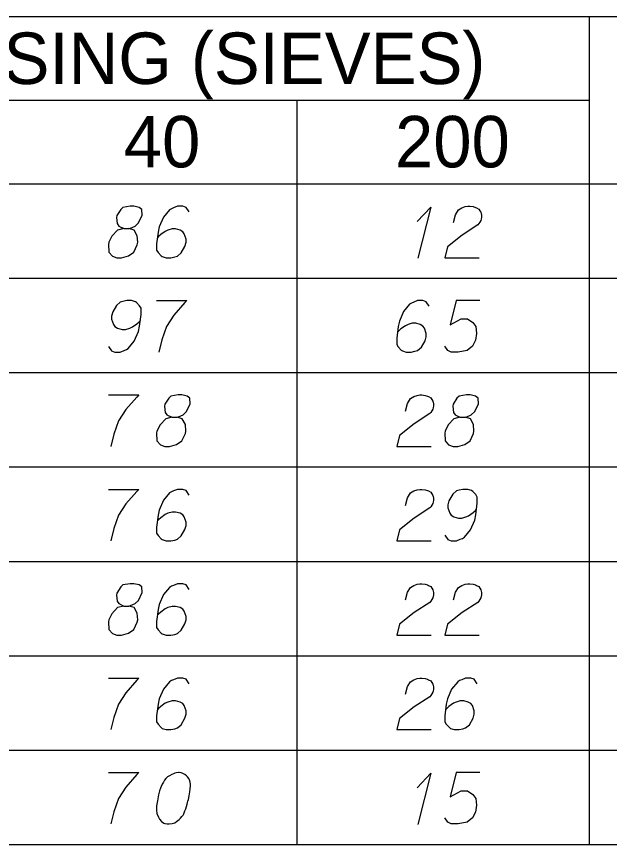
# Model space of a CAD drawing. Extents: x 2074207 to 2076812, y 516372 to 523312.
# Drawn here: x 2076678.5 to 2076733.8, y 517302 to 517379.2 of the extents above; entities that cross this region are included whole.
import ezdxf

# ---------------------------------------------------------------- set-up
doc = ezdxf.new("R2010")
doc.units = 0
for name, color, linetype in [('Prop DirtTable_ Soil Test Results - Outline (Major)', 7, 'Continuous'), ('Prop DirtTable_ Soil Test Results - Outline (Minor)', 7, 'Continuous'), ('Prop DirtTable_ Soil Test Results - Tx (Header - Small)', 7, 'Continuous'), ('Prop DirtTable_ Soil Test Results - Tx (Sample Data)', 7, 'Continuous')]:
    doc.layers.add(name, color=color, linetype=linetype)

msp = doc.modelspace()

# ---------------------------------------------------------------- linework, layer by layer
at = {"layer": 'Prop DirtTable_ Soil Test Results - Outline (Major)'}
for p, q in [((2076260.609, 517363.585), (2076811.903, 517363.585)), ((2076260.609, 517363.585), (2076811.903, 517363.585)), ((2076260.609, 517301.985), (2076811.903, 517301.985))]:
    msp.add_line(p, q, dxfattribs=at)
at = {"layer": 'Prop DirtTable_ Soil Test Results - Outline (Minor)'}
for p, q in [((2076260.609, 517379.185), (2076811.903, 517379.185)), ((2076731.93, 517379.185), (2076731.93, 517354.785)), ((2076526.074, 517371.385), (2076731.93, 517371.385)), ((2076704.671, 517371.385), (2076704.671, 517354.785)), ((2076260.609, 517354.785), (2076811.903, 517354.785)), ((2076260.609, 517354.785), (2076811.903, 517354.785)), ((2076704.671, 517354.785), (2076704.671, 517345.985)), ((2076731.93, 517354.785), (2076731.93, 517345.985)), ((2076260.609, 517345.985), (2076811.903, 517345.985)), ((2076260.609, 517345.985), (2076811.903, 517345.985)), ((2076704.671, 517345.985), (2076704.671, 517337.185)), ((2076731.93, 517345.985), (2076731.93, 517337.185)), ((2076260.609, 517337.185), (2076811.903, 517337.185)), ((2076260.609, 517337.185), (2076811.903, 517337.185)), ((2076704.671, 517337.185), (2076704.671, 517328.385)), ((2076731.93, 517337.185), (2076731.93, 517328.385)), ((2076260.609, 517328.385), (2076811.903, 517328.385)), ((2076260.609, 517328.385), (2076811.903, 517328.385)), ((2076704.671, 517328.385), (2076704.671, 517319.585)), ((2076731.93, 517328.385), (2076731.93, 517319.585)), ((2076260.609, 517319.585), (2076811.903, 517319.585)), ((2076260.609, 517319.585), (2076811.903, 517319.585)), ((2076704.671, 517319.585), (2076704.671, 517310.785)), ((2076731.93, 517319.585), (2076731.93, 517310.785)), ((2076260.609, 517310.785), (2076811.903, 517310.785)), ((2076260.609, 517310.785), (2076811.903, 517310.785)), ((2076704.671, 517310.785), (2076704.671, 517301.985)), ((2076731.93, 517310.785), (2076731.93, 517301.985)), ((2076260.609, 517301.985), (2076811.903, 517301.985))]:
    msp.add_line(p, q, dxfattribs=at)
at = {"layer": 'Prop DirtTable_ Soil Test Results - Tx (Sample Data)'}
for points in [[(2076688.527, 517359.419), (2076689.02, 517359.419), (2076689.162, 517359.457), (2076689.585, 517359.646), (2076689.902, 517359.948), (2076690.255, 517360.667), (2076690.22, 517361.196), (2076689.973, 517361.385), (2076689.479, 517361.498), (2076689.126, 517361.498), (2076688.456, 517361.385), (2076688.244, 517361.196), (2076687.892, 517360.629), (2076687.856, 517360.44), (2076687.927, 517359.873), (2076688.068, 517359.646), (2076688.527, 517359.419), (2076687.962, 517359.268), (2076687.433, 517358.701), (2076687.151, 517358.134), (2076687.116, 517357.945), (2076687.151, 517357.227), (2076687.468, 517356.849), (2076687.892, 517356.698), (2076688.315, 517356.698), (2076688.985, 517356.887), (2076689.479, 517357.227), (2076689.797, 517357.907), (2076689.832, 517358.134), (2076689.797, 517358.739), (2076689.514, 517359.268), (2076689.02, 517359.419)], [(2076694.629, 517360.969), (2076694.347, 517361.385), (2076694.03, 517361.498), (2076693.536, 517361.498), (2076693.183, 517361.347), (2076692.971, 517361.271), (2076692.795, 517361.158), (2076692.231, 517360.478), (2076691.843, 517359.57), (2076691.737, 517359.079), (2076691.596, 517357.983), (2076691.596, 517357.416), (2076691.737, 517357.189), (2076692.019, 517356.887), (2076692.125, 517356.811), (2076692.478, 517356.698), (2076692.936, 517356.698), (2076693.289, 517356.774), (2076693.536, 517356.849), (2076693.889, 517357.152), (2076694.241, 517357.756), (2076694.347, 517358.134), (2076694.347, 517358.437), (2076694.171, 517358.928), (2076694.03, 517359.117), (2076693.783, 517359.268), (2076693.359, 517359.381), (2076693.042, 517359.381), (2076692.654, 517359.268), (2076692.407, 517359.155), (2076691.984, 517358.852), (2076691.772, 517358.663), (2076691.666, 517358.55)], [(2076715.9, 517360.062), (2076717.17, 517361.422), (2076715.971, 517356.66)], [(2076719.287, 517359.986), (2076719.463, 517360.704), (2076719.746, 517361.158), (2076720.063, 517361.347), (2076720.38, 517361.46), (2076720.627, 517361.498), (2076720.804, 517361.498), (2076721.121, 517361.46), (2076721.333, 517361.385), (2076721.439, 517361.347), (2076721.65, 517361.233), (2076721.756, 517361.082), (2076721.827, 517360.931), (2076721.862, 517360.818), (2076721.897, 517360.667), (2076721.897, 517360.478), (2076721.862, 517360.289), (2076721.827, 517360.175), (2076721.756, 517360.024), (2076721.65, 517359.873), (2076721.545, 517359.759), (2076720.098, 517358.815), (2076718.723, 517357.718), (2076718.476, 517356.698), (2076721.686, 517356.698)], [(2076687.116, 517348.427), (2076687.398, 517348.011), (2076687.715, 517347.898), (2076688.209, 517347.898), (2076688.562, 517348.049), (2076688.774, 517348.125), (2076688.95, 517348.238), (2076689.514, 517348.918), (2076689.902, 517349.826), (2076690.008, 517350.317), (2076690.149, 517351.413), (2076690.149, 517351.98), (2076690.008, 517352.207), (2076689.726, 517352.509), (2076689.62, 517352.585), (2076689.267, 517352.698), (2076688.809, 517352.698), (2076688.456, 517352.622), (2076688.209, 517352.547), (2076687.856, 517352.244), (2076687.504, 517351.64), (2076687.398, 517351.262), (2076687.398, 517350.959), (2076687.574, 517350.468), (2076687.715, 517350.279), (2076687.962, 517350.128), (2076688.386, 517350.015), (2076688.703, 517350.015), (2076689.091, 517350.128), (2076689.338, 517350.241), (2076689.761, 517350.544), (2076689.973, 517350.733), (2076690.079, 517350.846)], [(2076691.596, 517352.698), (2076694.418, 517352.698), (2076694.241, 517352.509), (2076693.218, 517351.337), (2076692.513, 517350.279), (2076692.089, 517349.032), (2076691.807, 517347.898)], [(2076717.029, 517352.169), (2076716.747, 517352.585), (2076716.43, 517352.698), (2076715.936, 517352.698), (2076715.583, 517352.547), (2076715.371, 517352.471), (2076715.195, 517352.358), (2076714.631, 517351.678), (2076714.243, 517350.77), (2076714.137, 517350.279), (2076713.996, 517349.183), (2076713.996, 517348.616), (2076714.137, 517348.389), (2076714.419, 517348.087), (2076714.525, 517348.011), (2076714.878, 517347.898), (2076715.336, 517347.898), (2076715.689, 517347.974), (2076715.936, 517348.049), (2076716.289, 517348.352), (2076716.641, 517348.956), (2076716.747, 517349.334), (2076716.747, 517349.637), (2076716.571, 517350.128), (2076716.43, 517350.317), (2076716.183, 517350.468), (2076715.759, 517350.581), (2076715.442, 517350.581), (2076715.054, 517350.468), (2076714.807, 517350.355), (2076714.384, 517350.052), (2076714.172, 517349.863), (2076714.066, 517349.75)], [(2076721.756, 517352.698), (2076719.534, 517352.698), (2076718.969, 517350.43), (2076719.992, 517350.997), (2076720.592, 517350.997), (2076721.086, 517350.657), (2076721.368, 517350.279), (2076721.439, 517349.637), (2076721.333, 517348.994), (2076721.051, 517348.465), (2076720.557, 517348.049), (2076719.71, 517347.898), (2076719.075, 517347.898), (2076718.758, 517348.049), (2076718.476, 517348.465)], [(2076687.116, 517343.898), (2076689.938, 517343.898), (2076689.761, 517343.709), (2076688.738, 517342.537), (2076688.033, 517341.479), (2076687.609, 517340.232), (2076687.327, 517339.098)], [(2076693.007, 517341.819), (2076693.5, 517341.819), (2076693.642, 517341.857), (2076694.065, 517342.046), (2076694.382, 517342.348), (2076694.735, 517343.067), (2076694.7, 517343.596), (2076694.453, 517343.785), (2076693.959, 517343.898), (2076693.606, 517343.898), (2076692.936, 517343.785), (2076692.724, 517343.596), (2076692.372, 517343.029), (2076692.336, 517342.84), (2076692.407, 517342.273), (2076692.548, 517342.046), (2076693.007, 517341.819), (2076692.442, 517341.668), (2076691.913, 517341.101), (2076691.631, 517340.534), (2076691.596, 517340.345), (2076691.631, 517339.627), (2076691.948, 517339.249), (2076692.372, 517339.098), (2076692.795, 517339.098), (2076693.465, 517339.287), (2076693.959, 517339.627), (2076694.277, 517340.307), (2076694.312, 517340.534), (2076694.277, 517341.139), (2076693.994, 517341.668), (2076693.5, 517341.819)], [(2076714.807, 517342.386), (2076714.983, 517343.104), (2076715.266, 517343.558), (2076715.583, 517343.747), (2076715.9, 517343.86), (2076716.147, 517343.898), (2076716.324, 517343.898), (2076716.641, 517343.86), (2076716.853, 517343.785), (2076716.959, 517343.747), (2076717.17, 517343.633), (2076717.276, 517343.482), (2076717.347, 517343.331), (2076717.382, 517343.218), (2076717.417, 517343.067), (2076717.417, 517342.878), (2076717.382, 517342.689), (2076717.347, 517342.575), (2076717.276, 517342.424), (2076717.17, 517342.273), (2076717.065, 517342.159), (2076715.618, 517341.215), (2076714.243, 517340.118), (2076713.996, 517339.098), (2076717.206, 517339.098)], [(2076719.887, 517341.819), (2076720.38, 517341.819), (2076720.522, 517341.857), (2076720.945, 517342.046), (2076721.262, 517342.348), (2076721.615, 517343.067), (2076721.58, 517343.596), (2076721.333, 517343.785), (2076720.839, 517343.898), (2076720.486, 517343.898), (2076719.816, 517343.785), (2076719.604, 517343.596), (2076719.252, 517343.029), (2076719.216, 517342.84), (2076719.287, 517342.273), (2076719.428, 517342.046), (2076719.887, 517341.819), (2076719.322, 517341.668), (2076718.793, 517341.101), (2076718.511, 517340.534), (2076718.476, 517340.345), (2076718.511, 517339.627), (2076718.828, 517339.249), (2076719.252, 517339.098), (2076719.675, 517339.098), (2076720.345, 517339.287), (2076720.839, 517339.627), (2076721.157, 517340.307), (2076721.192, 517340.534), (2076721.157, 517341.139), (2076720.874, 517341.668), (2076720.38, 517341.819)], [(2076687.116, 517335.098), (2076689.938, 517335.098), (2076689.761, 517334.909), (2076688.738, 517333.737), (2076688.033, 517332.679), (2076687.609, 517331.432), (2076687.327, 517330.298)], [(2076694.629, 517334.569), (2076694.347, 517334.985), (2076694.03, 517335.098), (2076693.536, 517335.098), (2076693.183, 517334.947), (2076692.971, 517334.871), (2076692.795, 517334.758), (2076692.231, 517334.078), (2076691.843, 517333.17), (2076691.737, 517332.679), (2076691.596, 517331.583), (2076691.596, 517331.016), (2076691.737, 517330.789), (2076692.019, 517330.487), (2076692.125, 517330.411), (2076692.478, 517330.298), (2076692.936, 517330.298), (2076693.289, 517330.374), (2076693.536, 517330.449), (2076693.889, 517330.752), (2076694.241, 517331.356), (2076694.347, 517331.734), (2076694.347, 517332.037), (2076694.171, 517332.528), (2076694.03, 517332.717), (2076693.783, 517332.868), (2076693.359, 517332.981), (2076693.042, 517332.981), (2076692.654, 517332.868), (2076692.407, 517332.755), (2076691.984, 517332.452), (2076691.772, 517332.263), (2076691.666, 517332.15)], [(2076714.807, 517333.586), (2076714.983, 517334.304), (2076715.266, 517334.758), (2076715.583, 517334.947), (2076715.9, 517335.06), (2076716.147, 517335.098), (2076716.324, 517335.098), (2076716.641, 517335.06), (2076716.853, 517334.985), (2076716.959, 517334.947), (2076717.17, 517334.833), (2076717.276, 517334.682), (2076717.347, 517334.531), (2076717.382, 517334.418), (2076717.417, 517334.267), (2076717.417, 517334.078), (2076717.382, 517333.889), (2076717.347, 517333.775), (2076717.276, 517333.624), (2076717.17, 517333.473), (2076717.065, 517333.359), (2076715.618, 517332.415), (2076714.243, 517331.318), (2076713.996, 517330.298), (2076717.206, 517330.298)], [(2076718.476, 517330.827), (2076718.758, 517330.411), (2076719.075, 517330.298), (2076719.569, 517330.298), (2076719.922, 517330.449), (2076720.134, 517330.525), (2076720.31, 517330.638), (2076720.874, 517331.318), (2076721.262, 517332.226), (2076721.368, 517332.717), (2076721.509, 517333.813), (2076721.509, 517334.38), (2076721.368, 517334.607), (2076721.086, 517334.909), (2076720.98, 517334.985), (2076720.627, 517335.098), (2076720.169, 517335.098), (2076719.816, 517335.022), (2076719.569, 517334.947), (2076719.216, 517334.644), (2076718.864, 517334.04), (2076718.758, 517333.662), (2076718.758, 517333.359), (2076718.934, 517332.868), (2076719.075, 517332.679), (2076719.322, 517332.528), (2076719.746, 517332.415), (2076720.063, 517332.415), (2076720.451, 517332.528), (2076720.698, 517332.641), (2076721.121, 517332.944), (2076721.333, 517333.133), (2076721.439, 517333.246)], [(2076688.527, 517324.219), (2076689.02, 517324.219), (2076689.162, 517324.257), (2076689.585, 517324.446), (2076689.902, 517324.748), (2076690.255, 517325.467), (2076690.22, 517325.996), (2076689.973, 517326.185), (2076689.479, 517326.298), (2076689.126, 517326.298), (2076688.456, 517326.185), (2076688.244, 517325.996), (2076687.892, 517325.429), (2076687.856, 517325.24), (2076687.927, 517324.673), (2076688.068, 517324.446), (2076688.527, 517324.219), (2076687.962, 517324.068), (2076687.433, 517323.501), (2076687.151, 517322.934), (2076687.116, 517322.745), (2076687.151, 517322.027), (2076687.468, 517321.649), (2076687.892, 517321.498), (2076688.315, 517321.498), (2076688.985, 517321.687), (2076689.479, 517322.027), (2076689.797, 517322.707), (2076689.832, 517322.934), (2076689.797, 517323.539), (2076689.514, 517324.068), (2076689.02, 517324.219)], [(2076694.629, 517325.769), (2076694.347, 517326.185), (2076694.03, 517326.298), (2076693.536, 517326.298), (2076693.183, 517326.147), (2076692.971, 517326.071), (2076692.795, 517325.958), (2076692.231, 517325.278), (2076691.843, 517324.37), (2076691.737, 517323.879), (2076691.596, 517322.783), (2076691.596, 517322.216), (2076691.737, 517321.989), (2076692.019, 517321.687), (2076692.125, 517321.611), (2076692.478, 517321.498), (2076692.936, 517321.498), (2076693.289, 517321.574), (2076693.536, 517321.649), (2076693.889, 517321.952), (2076694.241, 517322.556), (2076694.347, 517322.934), (2076694.347, 517323.237), (2076694.171, 517323.728), (2076694.03, 517323.917), (2076693.783, 517324.068), (2076693.359, 517324.181), (2076693.042, 517324.181), (2076692.654, 517324.068), (2076692.407, 517323.955), (2076691.984, 517323.652), (2076691.772, 517323.463), (2076691.666, 517323.35)], [(2076714.807, 517324.786), (2076714.983, 517325.504), (2076715.266, 517325.958), (2076715.583, 517326.147), (2076715.9, 517326.26), (2076716.147, 517326.298), (2076716.324, 517326.298), (2076716.641, 517326.26), (2076716.853, 517326.185), (2076716.959, 517326.147), (2076717.17, 517326.033), (2076717.276, 517325.882), (2076717.347, 517325.731), (2076717.382, 517325.618), (2076717.417, 517325.467), (2076717.417, 517325.278), (2076717.382, 517325.089), (2076717.347, 517324.975), (2076717.276, 517324.824), (2076717.17, 517324.673), (2076717.065, 517324.559), (2076715.618, 517323.615), (2076714.243, 517322.518), (2076713.996, 517321.498), (2076717.206, 517321.498)], [(2076719.287, 517324.786), (2076719.463, 517325.504), (2076719.746, 517325.958), (2076720.063, 517326.147), (2076720.38, 517326.26), (2076720.627, 517326.298), (2076720.804, 517326.298), (2076721.121, 517326.26), (2076721.333, 517326.185), (2076721.439, 517326.147), (2076721.65, 517326.033), (2076721.756, 517325.882), (2076721.827, 517325.731), (2076721.862, 517325.618), (2076721.897, 517325.467), (2076721.897, 517325.278), (2076721.862, 517325.089), (2076721.827, 517324.975), (2076721.756, 517324.824), (2076721.65, 517324.673), (2076721.545, 517324.559), (2076720.098, 517323.615), (2076718.723, 517322.518), (2076718.476, 517321.498), (2076721.686, 517321.498)], [(2076687.116, 517317.498), (2076689.938, 517317.498), (2076689.761, 517317.309), (2076688.738, 517316.137), (2076688.033, 517315.079), (2076687.609, 517313.832), (2076687.327, 517312.698)], [(2076694.629, 517316.969), (2076694.347, 517317.385), (2076694.03, 517317.498), (2076693.536, 517317.498), (2076693.183, 517317.347), (2076692.971, 517317.271), (2076692.795, 517317.158), (2076692.231, 517316.478), (2076691.843, 517315.57), (2076691.737, 517315.079), (2076691.596, 517313.983), (2076691.596, 517313.416), (2076691.737, 517313.189), (2076692.019, 517312.887), (2076692.125, 517312.811), (2076692.478, 517312.698), (2076692.936, 517312.698), (2076693.289, 517312.774), (2076693.536, 517312.849), (2076693.889, 517313.152), (2076694.241, 517313.756), (2076694.347, 517314.134), (2076694.347, 517314.437), (2076694.171, 517314.928), (2076694.03, 517315.117), (2076693.783, 517315.268), (2076693.359, 517315.381), (2076693.042, 517315.381), (2076692.654, 517315.268), (2076692.407, 517315.155), (2076691.984, 517314.852), (2076691.772, 517314.663), (2076691.666, 517314.55)], [(2076714.807, 517315.986), (2076714.983, 517316.704), (2076715.266, 517317.158), (2076715.583, 517317.347), (2076715.9, 517317.46), (2076716.147, 517317.498), (2076716.324, 517317.498), (2076716.641, 517317.46), (2076716.853, 517317.385), (2076716.959, 517317.347), (2076717.17, 517317.233), (2076717.276, 517317.082), (2076717.347, 517316.931), (2076717.382, 517316.818), (2076717.417, 517316.667), (2076717.417, 517316.478), (2076717.382, 517316.289), (2076717.347, 517316.175), (2076717.276, 517316.024), (2076717.17, 517315.873), (2076717.065, 517315.759), (2076715.618, 517314.815), (2076714.243, 517313.718), (2076713.996, 517312.698), (2076717.206, 517312.698)], [(2076721.509, 517316.969), (2076721.227, 517317.385), (2076720.91, 517317.498), (2076720.416, 517317.498), (2076720.063, 517317.347), (2076719.851, 517317.271), (2076719.675, 517317.158), (2076719.111, 517316.478), (2076718.723, 517315.57), (2076718.617, 517315.079), (2076718.476, 517313.983), (2076718.476, 517313.416), (2076718.617, 517313.189), (2076718.899, 517312.887), (2076719.005, 517312.811), (2076719.358, 517312.698), (2076719.816, 517312.698), (2076720.169, 517312.774), (2076720.416, 517312.849), (2076720.769, 517313.152), (2076721.121, 517313.756), (2076721.227, 517314.134), (2076721.227, 517314.437), (2076721.051, 517314.928), (2076720.91, 517315.117), (2076720.663, 517315.268), (2076720.239, 517315.381), (2076719.922, 517315.381), (2076719.534, 517315.268), (2076719.287, 517315.155), (2076718.864, 517314.852), (2076718.652, 517314.663), (2076718.546, 517314.55)], [(2076687.116, 517308.698), (2076689.938, 517308.698), (2076689.761, 517308.509), (2076688.738, 517307.337), (2076688.033, 517306.279), (2076687.609, 517305.032), (2076687.327, 517303.898)], [(2076693.712, 517308.698), (2076693.642, 517308.698), (2076693.43, 517308.66), (2076693.289, 517308.622), (2076693.183, 517308.585), (2076693.007, 517308.509), (2076692.795, 517308.396), (2076692.619, 517308.282), (2076692.442, 517308.131), (2076692.336, 517307.98), (2076692.231, 517307.791), (2076692.125, 517307.602), (2076692.019, 517307.375), (2076691.948, 517307.224), (2076691.878, 517306.997), (2076691.772, 517306.619), (2076691.666, 517306.052), (2076691.596, 517305.599), (2076691.596, 517305.183), (2076691.631, 517304.881), (2076691.772, 517304.541), (2076691.878, 517304.352), (2076692.054, 517304.125), (2076692.266, 517303.974), (2076692.372, 517303.936), (2076692.583, 517303.898), (2076692.76, 517303.898), (2076693.042, 517303.936), (2076693.289, 517304.011), (2076693.465, 517304.125), (2076693.712, 517304.314), (2076693.818, 517304.427), (2076693.959, 517304.578), (2076694.065, 517304.729), (2076694.135, 517304.843), (2076694.206, 517305.032), (2076694.241, 517305.107), (2076694.312, 517305.296), (2076694.382, 517305.523), (2076694.453, 517305.75), (2076694.488, 517305.901), (2076694.523, 517306.015), (2076694.559, 517306.166), (2076694.629, 517306.506), (2076694.665, 517306.695), (2076694.7, 517306.884), (2076694.735, 517307.148), (2076694.77, 517307.489), (2076694.77, 517307.602), (2076694.735, 517307.753), (2076694.7, 517307.904), (2076694.594, 517308.131), (2076694.488, 517308.282), (2076694.382, 517308.396), (2076694.241, 517308.509), (2076694.1, 517308.585), (2076693.994, 517308.622), (2076693.889, 517308.66), (2076693.712, 517308.698)], [(2076715.9, 517307.262), (2076717.17, 517308.622), (2076715.971, 517303.86)], [(2076721.756, 517308.698), (2076719.534, 517308.698), (2076718.969, 517306.43), (2076719.992, 517306.997), (2076720.592, 517306.997), (2076721.086, 517306.657), (2076721.368, 517306.279), (2076721.439, 517305.637), (2076721.333, 517304.994), (2076721.051, 517304.465), (2076720.557, 517304.049), (2076719.71, 517303.898), (2076719.075, 517303.898), (2076718.758, 517304.049), (2076718.476, 517304.465)]]:
    msp.add_lwpolyline(points, dxfattribs=at)

# ---------------------------------------------------------------- texts
at = {"layer": 'Prop DirtTable_ Soil Test Results - Tx (Header - Small)'}
for s, height, p in [('% PASSING (SIEVES)', 4.79998, (2076656.984, 517372.896)), ('40', 4.8, (2076688.534, 517365.121)), ('200', 4.8, (2076713.832, 517365.121))]:
    msp.add_text(s, height=height, dxfattribs=at).set_placement(p)

doc.saveas('drawing.dxf')
